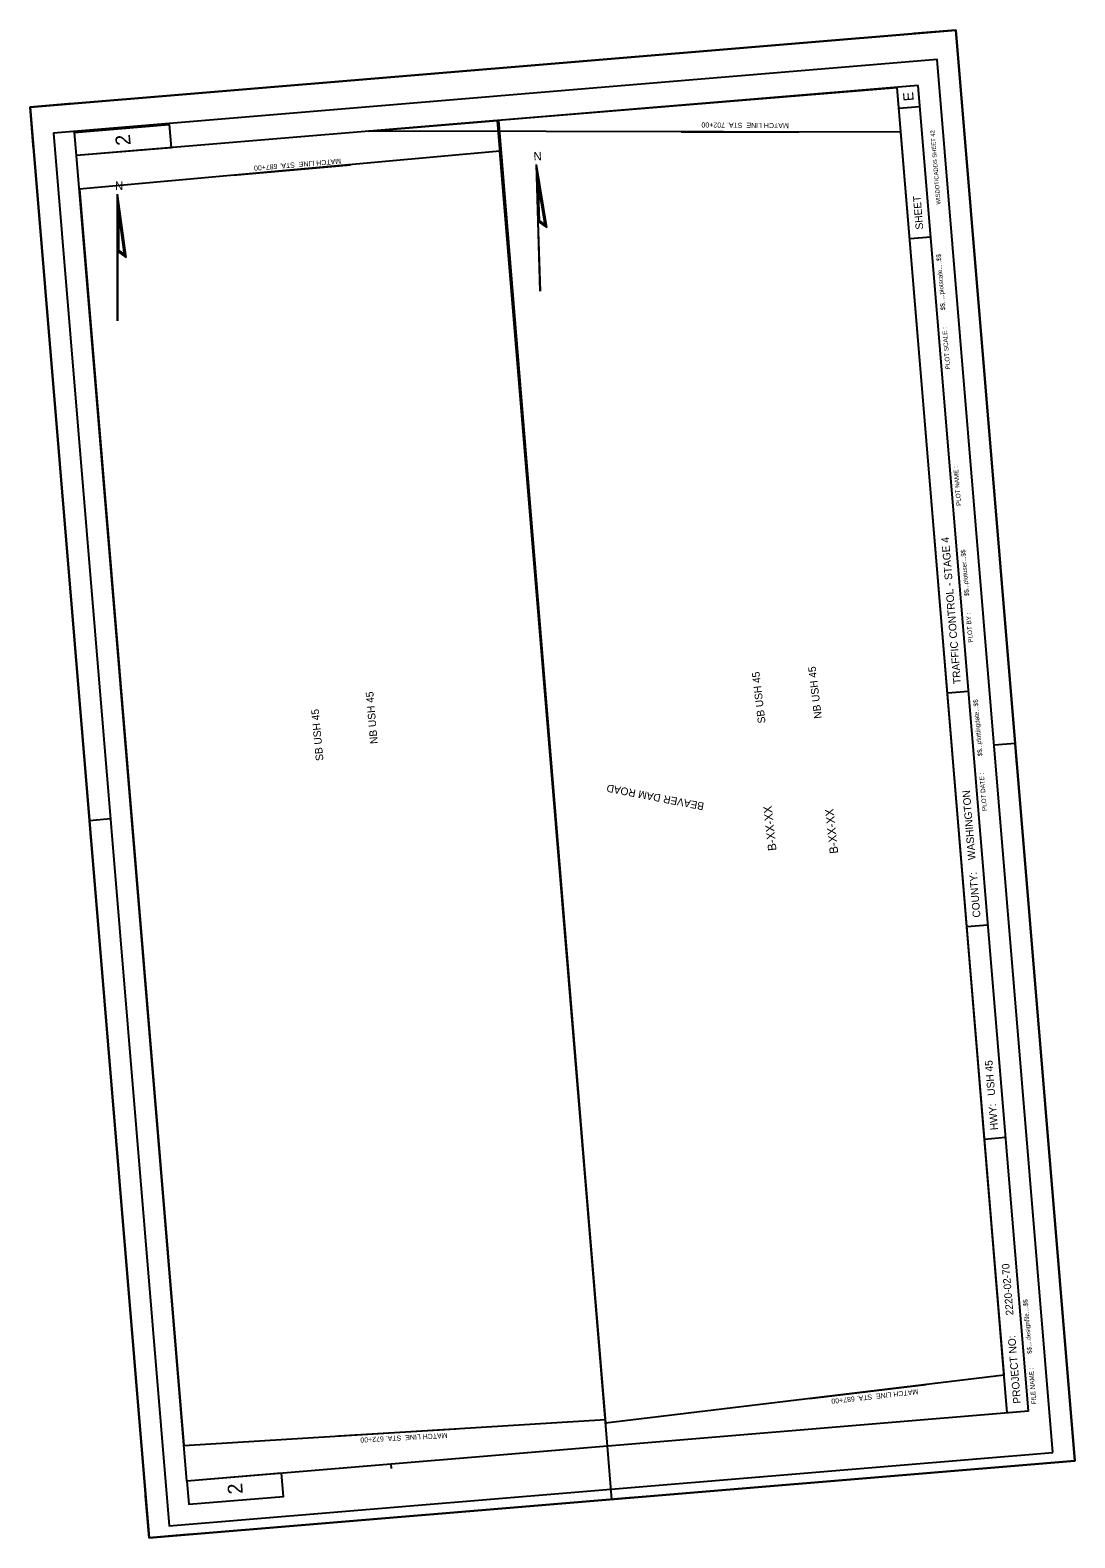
# Model space of a CAD drawing. Extents: x 354944 to 356181, y 189269 to 191054.
import ezdxf

# ---------------------------------------------------------------- set-up
doc = ezdxf.new("R2010")
doc.units = 0
for name, color, linetype in [('Default', 7, 'Continuous'), ('P_ALI_20', 7, 'Continuous'), ('P_ALI_200_Tic', 7, 'Continuous'), ('P_ALI_20_PIData', 7, 'Continuous'), ('P_ALI_20_Sta', 7, 'Continuous'), ('P_ALI_20_Tic', 7, 'Continuous'), ('P_ALI_50_Equation', 7, 'Continuous'), ('P_ALI_50_PIData', 7, 'Continuous'), ('P_ALI_50_Sta', 7, 'Continuous'), ('P_ALI_50_Tic', 7, 'Continuous')]:
    doc.layers.add(name, color=color, linetype=linetype)

msp = doc.modelspace()

# ---------------------------------------------------------------- linework, layer by layer
at = {"layer": 'Default'}
for points in [[(355625.8, 189405), (356097.7, 189461.8), (355975.3, 190933.6), (355345.5, 190934.5), (355497.6, 190947.1)], [(355625.8, 189405), (356097.7, 189461.8), (355975.3, 190933.6), (355345.5, 190934.5), (355497.6, 190947.1)], [(355625.8, 189405), (356097.7, 189461.8), (355975.3, 190933.6), (355345.5, 190934.5), (355497.6, 190947.1)], [(355126.3, 189378.4), (355625.5, 189409.1), (355500.6, 190910.8), (355002.6, 190866.1)], [(355126.3, 189378.4), (355625.5, 189409.1), (355500.6, 190910.8), (355002.6, 190866.1)], [(355126.3, 189378.4), (355625.5, 189409.1), (355500.6, 190910.8), (355002.6, 190866.1)]]:
    msp.add_lwpolyline(points, close=True, dxfattribs=at)
at = {"layer": 'P_ALI_20'}
msp.add_lwpolyline([(355085.2, 189268.9), (354944.3, 190963.1), (356040.6, 191054.2), (356181.4, 189360.1), (355085.2, 189268.9)], dxfattribs=at)
at = {"layer": 'P_ALI_200_Tic'}
msp.add_line((355628.1, 189377.5), (355499.4, 190947.3), dxfattribs=at)
msp.add_lwpolyline([(355971, 190985.9), (355498.5, 190947.2)], dxfattribs=at)
at = {"layer": 'P_ALI_20_PIData'}
for p, q in [((355556.1, 190820.4), (355543.8, 190895.1)), ((355545.9, 190827.6), (355543.8, 190895.1)), ((355546.6, 190828), (355544.9, 190883.8)), ((355555.1, 190822.1), (355544.9, 190883.8)), ((355547.4, 190828.4), (355546, 190872.5)), ((355554.1, 190823.7), (355546, 190872.5)), ((355057.9, 190785.2), (355047.9, 190860.2)), ((355047.9, 190792.7), (355047.9, 190860.2)), ((355048.6, 190793), (355048.6, 190848.9)), ((355056.9, 190786.8), (355048.6, 190848.9)), ((355049.4, 190793.4), (355049.4, 190837.6)), ((355055.9, 190788.5), (355049.4, 190837.6)), ((355545.9, 190827.6), (355556.1, 190820.4)), ((355548.4, 190745.1), (355545.9, 190827.6)), ((355548.7, 190745.2), (355546.1, 190827.4)), ((355546.6, 190828), (355555.1, 190822.1)), ((355547.4, 190828.4), (355554.1, 190823.7)), ((355047.9, 190792.7), (355057.9, 190785.2)), ((355047.9, 190710.2), (355047.9, 190792.7)), ((355048.1, 190710.2), (355048.1, 190792.5)), ((355048.6, 190793), (355056.9, 190786.8)), ((355049.4, 190793.4), (355055.9, 190788.5))]:
    msp.add_line(p, q, dxfattribs=at)
for points in [[(355543.8, 190895), (355543.8, 190895)], [(355047.9, 190860.1), (355047.9, 190860.1)]]:
    msp.add_lwpolyline(points, dxfattribs=at)
at = {"layer": 'P_ALI_20_Tic'}
msp.add_lwpolyline([(355085.2, 189268.9), (354944.3, 190963.1), (356040.6, 191054.2), (356181.4, 189360.1)], close=True, dxfattribs=at)
at = {"layer": 'P_ALI_50_Equation'}
for p, q in [((355715.2, 190933.9), (355854.5, 190933.7)), ((355184.9, 190882.5), (355323.6, 190894.9)), ((355867.1, 189434), (356005.4, 189450.7)), ((355309.6, 189389.7), (355448.6, 189398.2))]:
    msp.add_line(p, q, dxfattribs=at)
at = {"layer": 'P_ALI_50_Sta'}
for points in [[(356181.4, 189360.1), (356040.6, 191054.2), (354944.3, 190963.1), (355085.2, 189268.9)], [(356155.5, 189370), (356018.4, 191019.3), (354972, 190932.3), (355109.1, 189283)]]:
    msp.add_lwpolyline(points, close=True, dxfattribs=at)
at = {"layer": 'P_ALI_50_Tic'}
for p, q in [((356040.6, 191054.2), (355990.7, 191050.1)), ((356044.7, 191004.4), (356040.6, 191054.2)), ((355995.8, 190988.5), (354999.3, 190905.7)), ((356101.4, 189416.9), (355970.9, 190986.5)), ((356126.4, 189419), (355995.8, 190988.5)), ((354994.2, 190967.2), (354944.3, 190963.1)), ((354948.5, 190913.3), (354944.3, 190963.1)), ((355997.9, 190963.6), (355973, 190961.6)), ((355628.1, 189377.5), (355497.6, 190947.1)), ((355129.8, 189336.1), (354999.3, 190905.7)), ((356010.8, 190809.2), (355985.9, 190807.1)), ((356055.5, 190271), (356030.6, 190269)), ((356112.9, 190184.7), (356108.7, 190234.5)), ((356110.8, 190209.6), (356085.9, 190207.6)), ((355016.6, 190093.6), (355012.5, 190143.4)), ((355014.6, 190118.5), (355039.5, 190120.6)), ((356078.5, 189994.5), (356053.6, 189992.4)), ((356099.4, 189742.8), (356074.5, 189740.8)), ((356126.4, 189419), (355129.8, 189336.1)), ((355625, 189414.9), (355625, 189414.9)), ((356181.4, 189360.1), (356177.3, 189409.9)), ((355633.3, 189314.5), (355628.1, 189377.5)), ((355371.5, 189356.2), (355371.9, 189351.2)), ((356181.4, 189360.1), (356131.6, 189355.9)), ((355085.2, 189268.9), (355081.1, 189318.8)), ((355658.2, 189316.6), (355608.4, 189312.4)), ((355135, 189273.1), (355085.2, 189268.9))]:
    msp.add_line(p, q, dxfattribs=at)
for points in [[(354999.3, 190905.7), (354997, 190933.1), (355109.1, 190942.4), (355111.4, 190915)], [(355129.8, 189336.1), (355132.1, 189308.7), (355244.2, 189318), (355241.9, 189345.4)]]:
    msp.add_lwpolyline(points, close=True, dxfattribs=at)

# ---------------------------------------------------------------- texts
at = {"layer": 'P_ALI_20_PIData'}
msp.add_text('N', height=10, rotation=1.7466, dxfattribs=at).set_placement((355540.6, 190899.9))
msp.add_text('N', height=10, dxfattribs=at).set_placement((355044.8, 190865.1))
at = {"layer": 'P_ALI_20_Sta'}
for p in [(355828.2, 190083), (355901.3, 190079.6)]:
    msp.add_text('B-XX-XX', height=10, rotation=96.274, dxfattribs=at).set_placement(p)
at = {"layer": 'P_ALI_50_PIData'}
for s, height, rotation, p in [('MATCH LINE  STA. 702+00', 6, 179.5049, (355842.7, 190944.1)), ('MATCH LINE  STA. 687+00', 6, 184.7122, (355312.2, 190902.2)), ('NB USH 45', 9, 96.8942, (355881.9, 190239.5)), ('SB USH 45', 9, 96.8942, (355815.2, 190233.9)), ('NB USH 45', 9, 95.0701, (355356.1, 190209.4)), ('SB USH 45', 9, 95.2737, (355291.7, 190189.4)), ('BEAVER DAM ROAD', 9, 169.0755, (355742.9, 190139.2)), ('MATCH LINE  STA. 687+00', 6, 186.4588, (355995.5, 189445.1)), ('MATCH LINE  STA. 672+00', 6, 183.0972, (355438.4, 189393.2))]:
    msp.add_text(s, height=height, rotation=rotation, dxfattribs=at).set_placement(p)
at = {"layer": 'P_ALI_50_Tic'}
for s, height, rotation, p in [('E', 12, 94.7531, (355990.7, 190970.7)), ('2', 17.5, 94.7531, (355063.5, 190918.3)), ('WISDOT/CADDS SHEET 42', 5, 94.7531, (356022.6, 190848)), ('SHEET ', 9, 94.7531, (356002, 190818.5)), ('$$.....plotscale.....$$', 5.4, 94.7531, (356028, 190722.8)), ('PLOT SCALE : ', 5.4, 94.7531, (356033.8, 190652.8)), ('PLOT NAME :                      ', 5.4, 94.7531, (356046.8, 190491.1)), ('TRAFFIC CONTROL - STAGE 4', 9, 94.7531, (356046.7, 190280.3)), ('$$...plotuser...$$', 5.4, 94.753, (356056.2, 190384)), ('PLOT BY :', 5.4, 94.753, (356060.7, 190329.2)), ('$$...plottingdate...$$', 5.4, 94.753, (356071.9, 190194.6)), ('PLOT DATE :', 5.4, 94.753, (356077.3, 190129.8)), (' WASHINGTON', 9, 94.7531, (356064.3, 190068.6)), ('COUNTY:', 9, 94.7531, (356069.7, 190003.8)), (' USH 45', 9, 94.7531, (356087.5, 189789.5)), ('HWY:', 9, 94.7531, (356090.6, 189752.1)), (' 2220-02-70', 9, 94.7531, (356109.1, 189529.4)), ('$$....designfile....$$', 5.4, 94.753, (356130.7, 189487.1)), ('PROJECT NO:', 9, 94.7531, (356117.6, 189428.3)), ('FILE NAME :', 5.4, 94.7531, (356135.7, 189427.3)), ('2', 17.5, 94.7531, (355196.3, 189321.3))]:
    msp.add_text(s, height=height, rotation=rotation, dxfattribs=at).set_placement(p)

doc.saveas('drawing.dxf')
